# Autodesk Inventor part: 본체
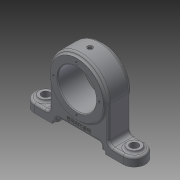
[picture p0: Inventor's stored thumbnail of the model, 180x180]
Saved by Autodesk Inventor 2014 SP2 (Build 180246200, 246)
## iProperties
Created: 2019-05
Part Number: 본체
Material: Generic
Document SubType Name: Modeling
Designer: gs
Density: 1 g/cm^3
Appearance: Default
Author: gs
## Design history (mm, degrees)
sketch "스케치1"
  geometry: L1 (0, 18)-(0, -18); L2 (0, 18)-(36, 18); L3 (36, 18)-(36, 15); L4 (36, 15)-(40, 15); L5 (40, 15)-(40, -15); L6 (40, -15)-(36, -15); L7 (36, -15)-(36, -18); L8 (36, -18)-(0, -18); 2 further points
  constraints: 16 end point, 3 perpendicular, 2 parallel, 1 coincident, 1 collinear, 1 midpoint, 1 vertical
  dimensions: "d0" = 36 distance of L1.start L1.end; "d2" = 36 distance of L1.start L2.end; "d3" = 3 distance of L2.end L3.end; "d4" = 4 distance of L3.end L4.end; "d5" = 30 distance of L4.end L5.end; "d6" = 4 distance of L5.end L6.end; "d7" = 3 distance of L6.end L7.end
revolve "회전1" sketch "스케치1" stored, may be unused: angle "d8" = 90 deg
sketch "스케치2"
  geometry: C1 r 36 at (0, 0) reference; 1 further point
  constraints: 1 coincident
hole "구멍1" sketch "스케치2" at (0, 0) diameter "d9" = 52; stored, may be unused: countersink angle "d13" = 90 deg, drill point angle "d15" = 118 deg; dims "d10" = 6, "d11" = 4, "d12" = 2, "d14" = 8
sketch "스케치3"
  geometry: C1 r 26 at (0, 0) reference; 1 further point
  constraints: 1 vertical alignment
  dimensions: "d16" = 31 distance of C1.centre point (0, 31)
hole "구멍2" sketch "스케치3" at (0, 31) diameter "d17" = 3.242; stored, may be unused: countersink angle "d21" = 90 deg, drill point angle "d23" = 118 deg; dims "d18" = 6, "d19" = 4, "d20" = 2, "d22" = 8
node "작업 평면1"
sketch "스케치4"
  geometry: 2 further points
  constraints: 1 coincident
hole "구멍3" sketch "스케치4" at (0, 0) diameter "d28" = 4.917; stored, may be unused: countersink angle "d32" = 90 deg, drill point angle "d34" = 118 deg; dims "d29" = 8, "d30" = 7, "d31" = 1, "d33" = 10
node "작업 평면2"
sketch "스케치5"
  geometry: 2 further points
  constraints: 1 coincident
hole "구멍4" sketch "스케치5" at (0, 0) diameter "d36" = 2; stored, may be unused: countersink angle "d40" = 90 deg, drill point angle "d42" = 118 deg; dims "d37" = 8, "d38" = 7, "d39" = 1, "d41" = 10
sketch "스케치6"
  geometry: C1 r 1.621 at (0, 31) reference; 2 further points
  constraints: 2 vertical alignment, 1 other
hole "구멍5" sketch "스케치6" at (0, 26) diameter "d43" = 3; stored, may be unused: countersink angle "d47" = 90 deg, drill point angle "d49" = 118 deg; dims "d44" = 8, "d45" = 7, "d46" = 1, "d48" = 10
chamfer "모따기1" distance "d50" = 1; stored, may be unused: second distance "d51" = 2, angle "d52" = 45 deg
node "작업 평면3"
sketch "스케치7"
  geometry: L1 (-40, 0)-(-40, -48); L2 (-40, -48)-(-75, -48); L3 (-75, -48)-(-75, -60); L4 (-75, -60)-(-36, -60); L5 (-36, -60)-(-36, -56); L6 (-36, -56)-(-30, -56); L7 (-30, -56)-(-30, -50); L8 (-30, -50)-(30, -50); L9 (30, -50)-(30, -56); L10 (30, -56)-(36, -56); L11 (36, -56)-(36, -60); L12 (36, -60)-(75, -60); L13 (75, -60)-(75, -48); L14 (75, -48)-(40, -48); L15 (40, -48)-(40, 0); A1 r 40 centre (0, 0) between (-40, 0) and (40, 0) reference; 1 further point
  constraints: 30 end point, 11 parallel, 7 equal length, 7 horizontal alignment, 3 perpendicular, 2 point on circle, 1 tangent, 1 vertical
  dimensions: "d55" = 10 distance from line of L8 L4.end; "d56" = 4 distance of L4.end L5.end; "d57" = 12 distance of L2.end L3.end; "d58" = 72 distance of L11.end L4.end; "d59" = 60 distance of L9.end L6.end; "d62" = 60 vertical distance of L3.end L1.start; "d64" = 75 horizontal distance of L13.end point (0, 0)
extrude "돌출1" join sketch "스케치7" stored distance "d66" = 30; taper "d67" = 0 deg
fillet "모깎기1" dims "d68" = 15
fillet "모깎기2" dims "d69" = 6
fillet "모깎기3" dims "d70" = 3
sketch "스케치9"
  geometry: L1 (14, 0)-(0, 0) reference; L2 (0, 24)-(14, 24) reference; L3 (14, 0)-(14, 24) reference; L4 (99.292, -3)-(20.708, -3) reference; L5 (106, 0)-(106, 24) reference; L6 (20.708, 27)-(99.292, 27) reference; L7 (120, 0)-(106, 0) reference; L8 (106, 24)-(120, 24) reference; C1 r 9 at (0, 12); A1 r 12 centre (0, 12) between (0, 24) and (0, 0) reference; A2 r 12 centre (120, 12) between (120, 0) and (120, 24) reference; A3 r 15 centre (0, 12) between (0, 27) and (0, -3) reference; A4 r 15 centre (120, 12) between (120, -3) and (120, 27) reference; 1 further point
  constraints: 1 centre point, 1 horizontal alignment, 4 other
  dimensions: "d79" = 18 diameter of C1; "d80" = 60 distance of point (60, 12) C1.centre
extrude "돌출2" join sketch "스케치9" distance "d82" = 3; taper "d83" = 0 deg
sketch "스케치10"
  geometry: C1 r 9 at (0, 0) reference; 2 further points
  constraints: 1 coincident
hole "구멍7" sketch "스케치10" at (0, 0) diameter "d84" = 11; stored, may be unused: countersink angle "d88" = 90 deg, drill point angle "d90" = 118 deg; dims "d85" = 8, "d86" = 7, "d87" = 1, "d89" = 10
fillet "모깎기4" dims "d91" = 3
sketch "스케치11"
  geometry: C1 r 9 at (14, 12); A1 r 12 centre (14, 12) between (14, 0) and (14, 24) reference; 1 further point
  constraints: 1 centre point, 1 coincident
  dimensions: "d92" = 18 diameter of C1
extrude "돌출3" join sketch "스케치11" distance "d93" = 3; taper "d94" = 0 deg
sketch "스케치12"
  geometry: C1 r 9 at (0, 0) reference; 2 further points
  constraints: 1 coincident
hole "구멍8" sketch "스케치12" at (0, 0) diameter "d95" = 11; stored, may be unused: countersink angle "d99" = 90 deg, drill point angle "d101" = 118 deg; dims "d96" = 8, "d97" = 7, "d98" = 1, "d100" = 10
fillet "모깎기5" dims "d102" = 3
fillet "모깎기6" dims "d103" = 3
fillet "모깎기7" dims "d104" = 3
sketch "스케치13"
  geometry: L1 (9, 10)-(63, 10) reference; A1 r 39 centre (36, 60) between (-1, 47.671) and (73, 47.671) reference; 1 further point
  constraints: 1 vertical alignment, 1 other
  dimensions: "d105" = 7 distance from line of L1 point (36, 17)
feature "엠보싱1" sketch "스케치13" dims "d19" = 4, "d106" = 0.5, "d107" = 0
node "솔리드1"
pattern_circular "원형 패턴1" dims angle "d25" = 360 deg
mirror "대칭1"
node "절단 모서리 투영1"
other parameters: "d35" = 26, "d53" = 0
